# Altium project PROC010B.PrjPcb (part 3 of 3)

## Sheet PROC010C_XDS110 Interface_1B.SchDoc: XDS110 Interface_1B
size 431 x 279 mm; Date: Not shown in title block; ApprovedBy: Not shown in title block; CheckedBy: Not shown in title block; Author: Not shown in title block; CompanyName: Not shown in title block; DrawnBy: Adrian Ozer; Engineer: Not shown in title block; Organization: Not shown in title block; Address1: Not shown in title block; Address2: Not shown in title block; Address3: Not shown in title block; Address4: Not shown in title block; DocumentNumber: 13; Revision: Use project parameter SCH_Rev; SheetNumber: 13; SheetTotal: 16; PageSetup: Record=PageOptions¦CenterHorizontal=True¦CenterVertical=True¦PrintScale=1.00¦XCorrection=1.00¦YCorrection=1.00¦PrintKind=0¦BorderSize=5000000¦LeftOffset=0¦BottomOffset=0¦Orientation=2¦PaperLength=1000¦PaperWidth=1000¦Scale=100¦PaperSource=15¦PrintQuality=600¦MediaType=1¦DitherType=10¦PaperKind=Letter¦PrintScaleMode=1
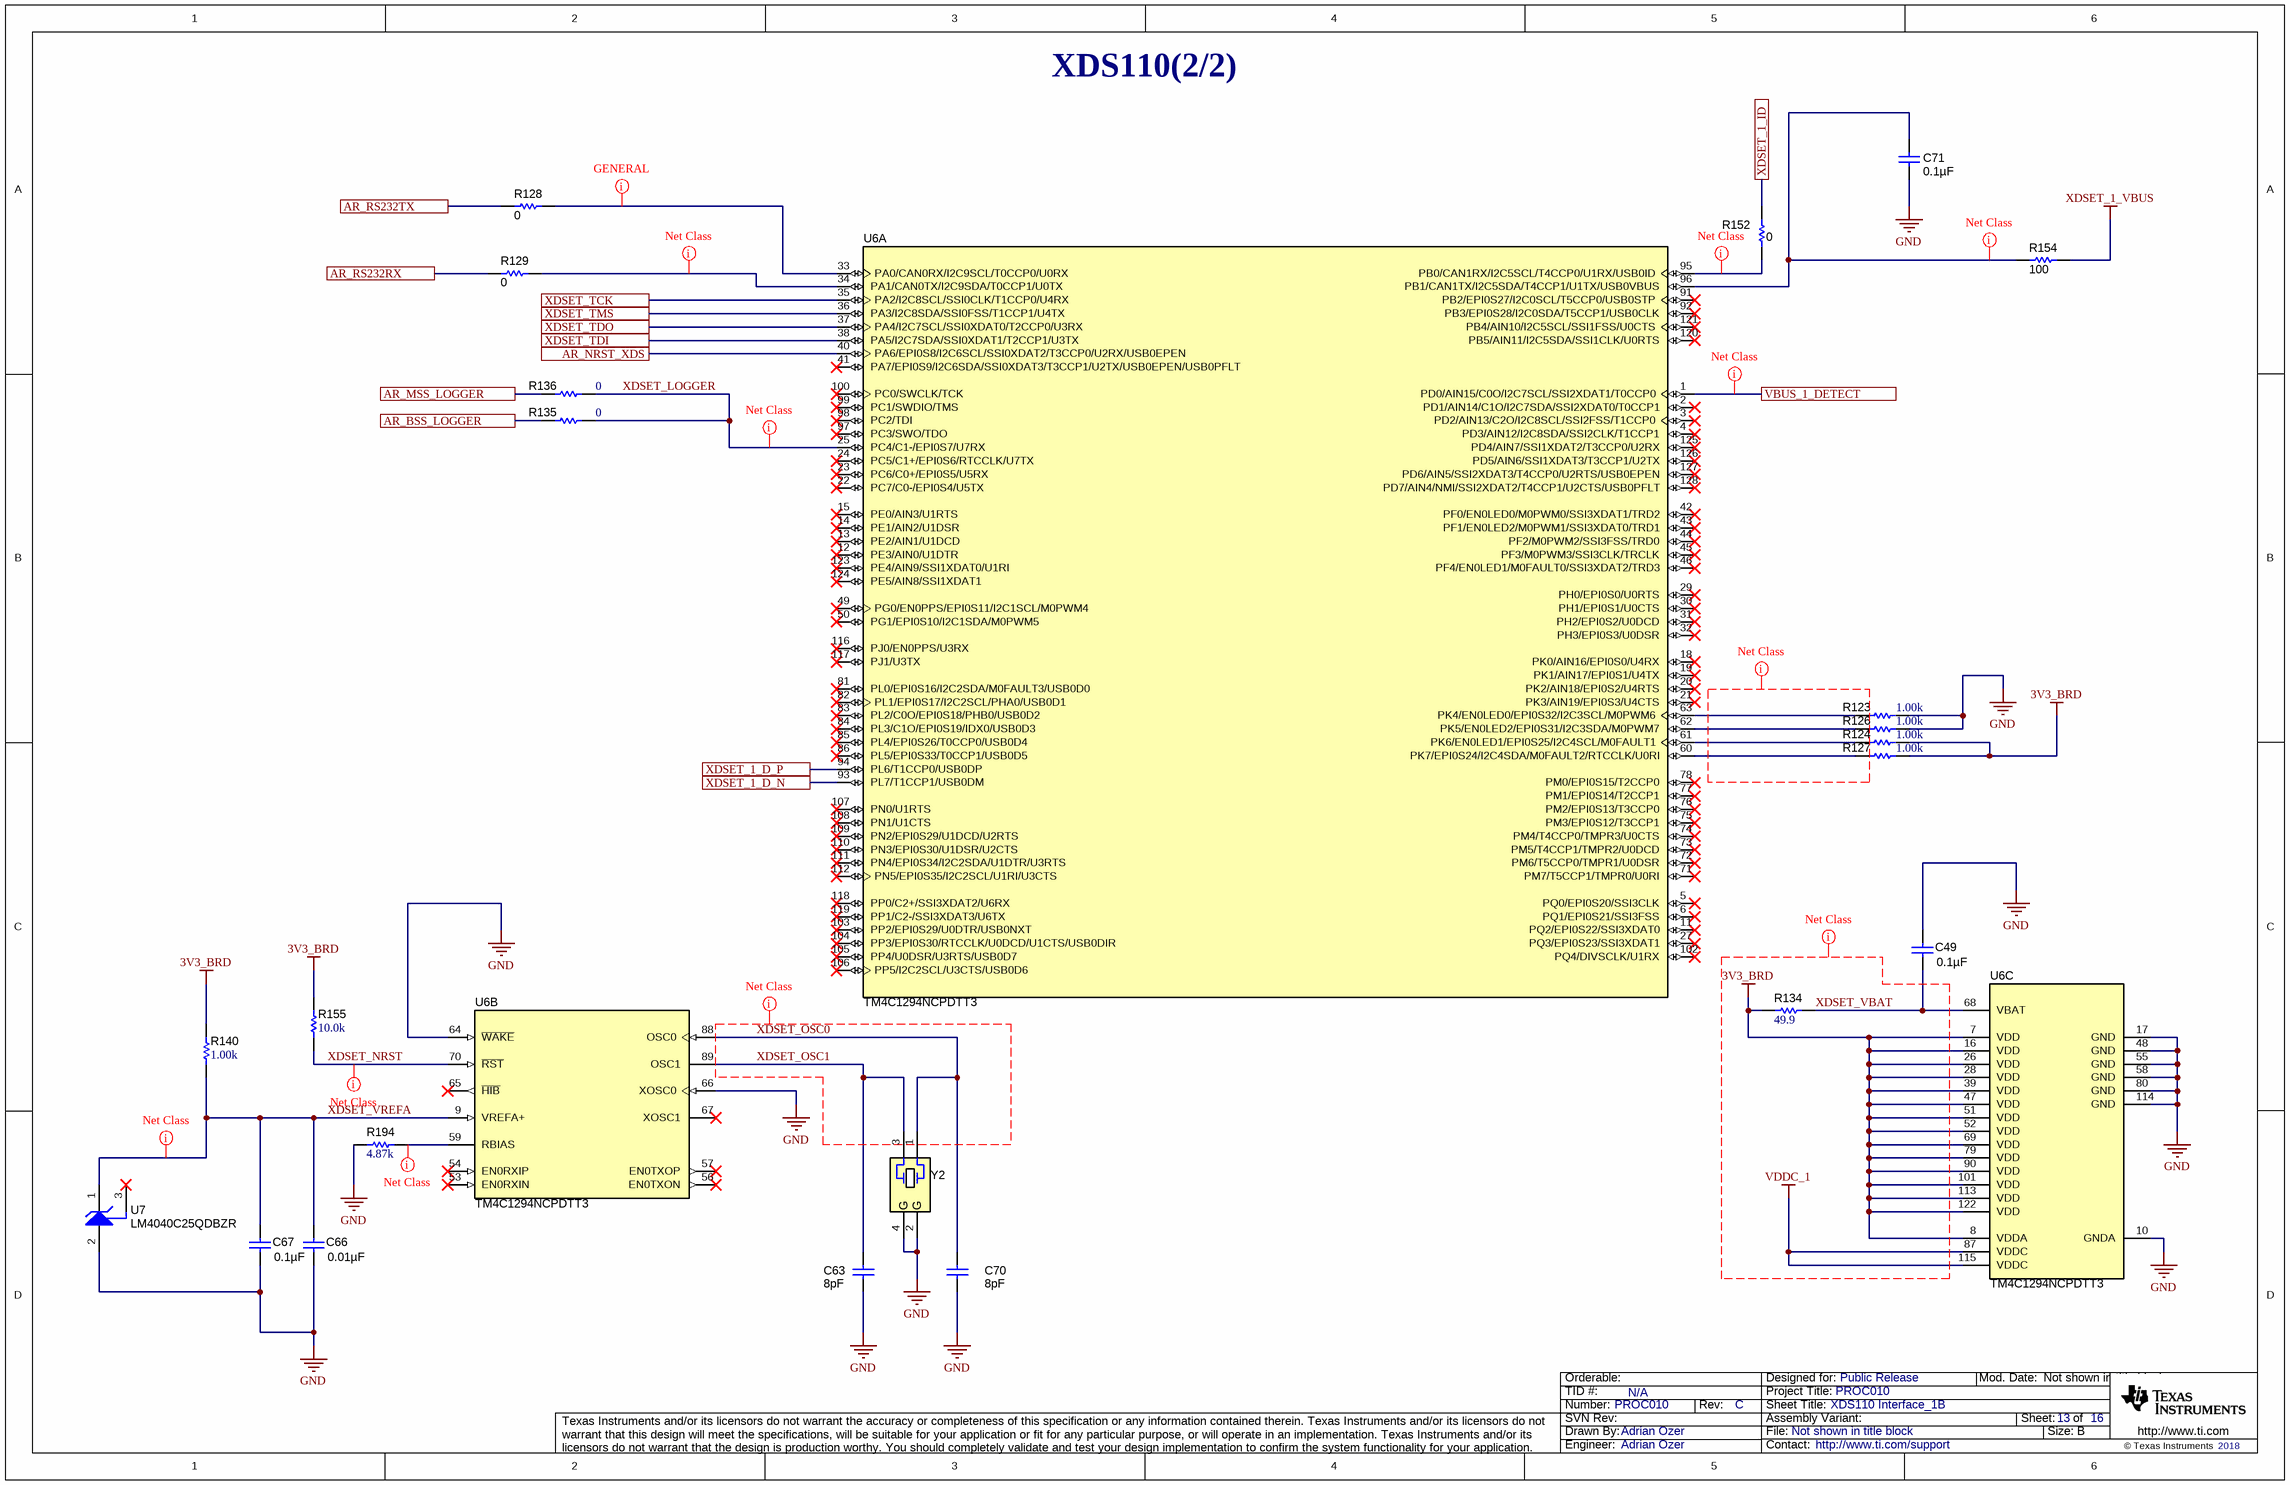
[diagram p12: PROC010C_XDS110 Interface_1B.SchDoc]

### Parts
C49  ValueDisplayed: 0.1µF  [0402L]  (hidden comment: C0402C104K8RACTU)
C63  ValueDisplayed: 8pF  [0402L]  (hidden comment: GRM1555C1H8R0DA01D)
C66  ValueDisplayed: 0.01µF  [0402L]  (hidden comment: C0402C103K4RACTU)
C67  ValueDisplayed: 0.1µF  [0402L]  (hidden comment: C0402C104K8RACTU)
C70  ValueDisplayed: 8pF  [0402L]  (hidden comment: GRM1555C1H8R0DA01D)
C71  ValueDisplayed: 0.1µF  [0402L]  (hidden comment: C0402C104K8RACTU)
R123  ValueDisplayed: 1.00k  [0402L]  (hidden comment: CRCW04021K00FKED)
R124  ValueDisplayed: 1.00k  [0402L]  (hidden comment: CRCW04021K00FKED)
R126  ValueDisplayed: 1.00k  [0402L]  (hidden comment: CRCW04021K00FKED)
R127  ValueDisplayed: 1.00k  [0402L]  (hidden comment: CRCW04021K00FKED)
R128  ValueDisplayed: 0  [0402L]  (hidden comment: ERJ-2GE0R00X)
R129  ValueDisplayed: 0  [0402L]  (hidden comment: ERJ-2GE0R00X)
R134  ValueDisplayed: 49.9  [0402L]  (hidden comment: CRCW040249R9FKED)
R135  ValueDisplayed: 0  [0201_Silk]  (hidden comment: CRCW02010000Z0ED)
R136  ValueDisplayed: 0  [0201_Silk]  (hidden comment: CRCW02010000Z0ED)
R140  ValueDisplayed: 1.00k  [0402L]  (hidden comment: CRCW04021K00FKED)
R152  ValueDisplayed: 0  [0402L]  (hidden comment: ERJ-2GE0R00X)
R154  ValueDisplayed: 100  [0402L]  (hidden comment: ERJ-2GEJ101X)
R155  ValueDisplayed: 10.0k  [0402L]  (hidden comment: CRCW040210K0FKED)
R194  ValueDisplayed: 4.87k  [0402L]  (hidden comment: CRCW04024K87FKED)
U6  TM4C1294NCPDTT3  [PDT0128A]  (parts A,B,C of 3)
U7  LM4040C25QDBZR  [DBZ0003A_N]
Y2  NX3225SA-16.000M-STD-CRS-2  [NDK_NX3225SA]  (value not drawn)

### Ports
AR_BSS_LOGGER, AR_MSS_LOGGER, AR_NRST_XDS, AR_RS232RX, AR_RS232TX, VBUS_1_DETECT, XDSET_1_D_N, XDSET_1_D_P, XDSET_1_ID, XDSET_TCK, XDSET_TDI, XDSET_TDO, XDSET_TMS

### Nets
3V3_BRD: R124.2 R127.2 R134.2 R140.2 R155.2 U6.7(VDD) U6.8(VDDA) U6.16(VDD) U6.26(VDD) U6.28(VDD) U6.39(VDD) U6.47(VDD) U6.51(VDD) U6.52(VDD) U6.69(VDD) U6.79(VDD) U6.90(VDD) U6.101(VDD) U6.113(VDD) U6.122(VDD)
GND: C49.1 C63.1 C66.1 C67.1 C70.1 C71.1 R123.2 R126.2 R194.1 U6.10(GNDA) U6.17(GND) U6.48(GND) U6.55(GND) U6.58(GND) U6.64(~{WAKE}) U6.66(XOSC0) U6.80(GND) U6.114(GND) U7.2(ANODE) Y2.2(GND) Y2.4(GND)
VDDC_1: U6.87(VDDC) U6.115(VDDC)
XDSET_1_VBUS: R154.2
AR_BSS_LOGGER: R135.1 ; port AR_BSS_LOGGER
AR_MSS_LOGGER: R136.1 ; port AR_MSS_LOGGER
AR_NRST_XDS: U6.40(PA6/EPI0S8/I2C6SCL/SSI0XDAT2/T3CCP0/U2RX/USB0EPEN) ; port AR_NRST_XDS
AR_RS232RX: R129.1 ; port AR_RS232RX
AR_RS232TX: R128.1 ; port AR_RS232TX
VBUS_1_DETECT: U6.1(PD0/AIN15/C0O/I2C7SCL/SSI2XDAT1/T0CCP0) ; port VBUS_1_DETECT
XDSET_1_D_N: U6.93(PL7/T1CCP1/USB0DM) ; port XDSET_1_D_N
XDSET_1_D_P: U6.94(PL6/T1CCP0/USB0DP) ; port XDSET_1_D_P
XDSET_1_ID: R152.2 ; port XDSET_1_ID
XDSET_LOGGER: R135.2 R136.2 U6.25(PC4/C1-/EPI0S7/U7RX)
XDSET_NRST: R155.1 U6.70(~{RST})
XDSET_OSC0: C70.2 U6.88(OSC0) Y2.1
XDSET_OSC1: C63.2 U6.89(OSC1) Y2.3
XDSET_TCK: U6.35(PA2/I2C8SCL/SSI0CLK/T1CCP0/U4RX) ; port XDSET_TCK
XDSET_TDI: U6.38(PA5/I2C7SDA/SSI0XDAT1/T2CCP1/U3TX) ; port XDSET_TDI
XDSET_TDO: U6.37(PA4/I2C7SCL/SSI0XDAT0/T2CCP0/U3RX) ; port XDSET_TDO
XDSET_TMS: U6.36(PA3/I2C8SDA/SSI0FSS/T1CCP1/U4TX) ; port XDSET_TMS
XDSET_VBAT: C49.2 R134.1 U6.68(VBAT)
XDSET_VREFA: C66.2 C67.2 R140.1 U6.9(VREFA+) U7.1(CATHODE)
NetC71_2: C71.2 R154.1 U6.96(PB1/CAN1TX/I2C5SDA/T4CCP1/U1TX/USB0VBUS)
NetR123_1: R123.1 U6.63(PK4/EN0LED0/EPI0S32/I2C3SCL/M0PWM6)
NetR124_1: R124.1 U6.61(PK6/EN0LED1/EPI0S25/I2C4SCL/M0FAULT1)
NetR126_1: R126.1 U6.62(PK5/EN0LED2/EPI0S31/I2C3SDA/M0PWM7)
NetR127_1: R127.1 U6.60(PK7/EPI0S24/I2C4SDA/M0FAULT2/RTCCLK/U0RI)
NetR128_2: R128.2 U6.33(PA0/CAN0RX/I2C9SCL/T0CCP0/U0RX)
NetR129_2: R129.2 U6.34(PA1/CAN0TX/I2C9SDA/T0CCP1/U0TX)
NetR152_1: R152.1 U6.95(PB0/CAN1RX/I2C5SCL/T4CCP0/U1RX/USB0ID)
NetR194_2: R194.2 U6.59(RBIAS)

Not connected (* = marked no-connect by the designer): U6 2(PD1/AIN14/C1O/I2C7SDA/SSI2XDAT0/T0CCP1)* 3(PD2/AIN13/C2O/I2C8SCL/SSI2FSS/T1CCP0)* 4(PD3/AIN12/I2C8SDA/SSI2CLK/T1CCP1)* 5(PQ0/EPI0S20/SSI3CLK)* 6(PQ1/EPI0S21/SSI3FSS)* 11(PQ2/EPI0S22/SSI3XDAT0)* 12(PE3/AIN0/U1DTR)* 13(PE2/AIN1/U1DCD)* 14(PE1/AIN2/U1DSR)* 15(PE0/AIN3/U1RTS)* 18(PK0/AIN16/EPI0S0/U4RX)* 19(PK1/AIN17/EPI0S1/U4TX)* 20(PK2/AIN18/EPI0S2/U4RTS)* 21(PK3/AIN19/EPI0S3/U4CTS)* 22(PC7/C0-/EPI0S4/U5TX)* 23(PC6/C0+/EPI0S5/U5RX)* 24(PC5/C1+/EPI0S6/RTCCLK/U7TX)* 27(PQ3/EPI0S23/SSI3XDAT1)* 29(PH0/EPI0S0/U0RTS)* 30(PH1/EPI0S1/U0CTS)* 31(PH2/EPI0S2/U0DCD)* 32(PH3/EPI0S3/U0DSR)* 41(PA7/EPI0S9/I2C6SDA/SSI0XDAT3/T3CCP1/U2TX/USB0EPEN/USB0PFLT)* 42(PF0/EN0LED0/M0PWM0/SSI3XDAT1/TRD2)* 43(PF1/EN0LED2/M0PWM1/SSI3XDAT0/TRD1)* 44(PF2/M0PWM2/SSI3FSS/TRD0)* 45(PF3/M0PWM3/SSI3CLK/TRCLK)* 46(PF4/EN0LED1/M0FAULT0/SSI3XDAT2/TRD3)* 49(PG0/EN0PPS/EPI0S11/I2C1SCL/M0PWM4)* 50(PG1/EPI0S10/I2C1SDA/M0PWM5)* 53(EN0RXIN)* 54(EN0RXIP)* 56(EN0TXON)* 57(EN0TXOP)* 65(~{HIB})* 67(XOSC1)* 71(PM7/T5CCP1/TMPR0/U0RI)* 72(PM6/T5CCP0/TMPR1/U0DSR)* 73(PM5/T4CCP1/TMPR2/U0DCD)* 74(PM4/T4CCP0/TMPR3/U0CTS)* 75(PM3/EPI0S12/T3CCP1)* 76(PM2/EPI0S13/T3CCP0)* 77(PM1/EPI0S14/T2CCP1)* 78(PM0/EPI0S15/T2CCP0)* 81(PL0/EPI0S16/I2C2SDA/M0FAULT3/USB0D0)* 82(PL1/EPI0S17/I2C2SCL/PHA0/USB0D1)* 83(PL2/C0O/EPI0S18/PHB0/USB0D2)* 84(PL3/C1O/EPI0S19/IDX0/USB0D3)* 85(PL4/EPI0S26/T0CCP0/USB0D4)* 86(PL5/EPI0S33/T0CCP1/USB0D5)* 91(PB2/EPI0S27/I2C0SCL/T5CCP0/USB0STP)* 92(PB3/EPI0S28/I2C0SDA/T5CCP1/USB0CLK)* 97(PC3/SWO/TDO)* 98(PC2/TDI)* 99(PC1/SWDIO/TMS)* 100(PC0/SWCLK/TCK)* 102(PQ4/DIVSCLK/U1RX)* 103(PP2/EPI0S29/U0DTR/USB0NXT)* 104(PP3/EPI0S30/RTCCLK/U0DCD/U1CTS/USB0DIR)* 105(PP4/U0DSR/U3RTS/USB0D7)* 106(PP5/I2C2SCL/U3CTS/USB0D6)* 107(PN0/U1RTS)* 108(PN1/U1CTS)* 109(PN2/EPI0S29/U1DCD/U2RTS)* 110(PN3/EPI0S30/U1DSR/U2CTS)* 111(PN4/EPI0S34/I2C2SDA/U1DTR/U3RTS)* 112(PN5/EPI0S35/I2C2SCL/U1RI/U3CTS)* 116(PJ0/EN0PPS/U3RX)* 117(PJ1/U3TX)* 118(PP0/C2+/SSI3XDAT2/U6RX)* 119(PP1/C2-/SSI3XDAT3/U6TX)* 120(PB5/AIN11/I2C5SDA/SSI1CLK/U0RTS)* 121(PB4/AIN10/I2C5SCL/SSI1FSS/U0CTS)* 123(PE4/AIN9/SSI1XDAT0/U1RI)* 124(PE5/AIN8/SSI1XDAT1)* 125(PD4/AIN7/SSI1XDAT2/T3CCP0/U2RX)* 126(PD5/AIN6/SSI1XDAT3/T3CCP1/U2TX)* 127(PD6/AIN5/SSI2XDAT3/T4CCP0/U2RTS/USB0EPEN)* 128(PD7/AIN4/NMI/SSI2XDAT2/T4CCP1/U2CTS/USB0PFLT)*; U7 3(NC)*

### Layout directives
net class GENERAL: (no net found under the mark), NetC71_2, NetR129_2, NetR152_1, NetR194_2, VBUS_1_DETECT, XDSET_LOGGER, XDSET_NRST
net class PWR: 3V3_BRD, VDDC_1, XDSET_VBAT, XDSET_VREFA
net class CLK: GND, XDSET_OSC0, XDSET_OSC1
net class Undefined: NetR128_2

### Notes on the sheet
- XDS110(2/2)

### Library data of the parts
C49 = CMP-0078241-1: CAP, CERM, 0.1 µF, 10 V,+/- 10%, X7R, 0402; Manufacturer: Kemet; TaMin_C: -55°C; Polarized: N; SizeAreaWB_mm2: 3; U/M: EA; Value: 0.1uF; TaMax_C: 125°C; SizeZ_mm: 0.6; SizeX_mm: 1; SizeY_mm: 0.5; Cap_Case: 0402; Value2: 10V; CompType: Capacitor; Cap_F: 100nF; AEC Category: Q200
C63 C70 = CMP-0006494-2: CAP, CERM, 8 pF, 50 V, +/- 6%, C0G/NP0, 0402; Manufacturer: MuRata; TaMin_C: -55°C; Polarized: N; SizeAreaWB_mm2: 3; Value1: Unknown; U/M: EA; Value: 8pF; TaMax_C: 125°C; SizeZ_mm: 0.6; SizeX_mm: 1; SizeY_mm: 0.5; Cap_Case: 0402; Value2: 50V; CompType: Capacitor; AEC Category: Q200
C66 = CMP-0078218-1: CAP, CERM, 0.01 µF, 16 V,+/- 10%, X7R, 0402; Manufacturer: Kemet; TaMin_C: -55°C; Polarized: N; Green_Lifecycle: Active; SizeAreaWB_mm2: 3; Green_REACh: Passed; U/M: EA; Value: 0.01uF; TaMax_C: 125°C; SizeZ_mm: 0.6; SizeX_mm: 1; SizeY_mm: 0.5; Cap_Case: 0402; Value2: 16V; Cap_F: 10nF; AEC Category: Q200
C67 C71 = CMP-0078241-1: CAP, CERM, 0.1 µF, 10 V,+/- 10%, X7R, 0402; Manufacturer: Kemet; TaMin_C: -55°C; Polarized: N; SizeAreaWB_mm2: 3; U/M: EA; Value: 0.1uF; TaMax_C: 125°C; SizeZ_mm: 0.6; SizeX_mm: 1; SizeY_mm: 0.5; Cap_Case: 0402; Value2: 10V; Cap_F: 100nF; AEC Category: Q200
R123 R124 R126 R127 R140 = CMP-0026071-3: RES, 1.00 k, 1%, 0.063 W, AEC-Q200 Grade 0, 0402; Manufacturer: Vishay-Dale; Power_W: 63mW; TempCo: 100 ppm/C; Value_Code: 1k00; Value: 1.00k; EIA_Code: E96; Res_ohm: 1k; SizeX_mm: 1; SizeY_mm: 0.5; SizeZ_mm: 0.6; Value2: 0.063W; AEC Qualified: Y; VDC_V: 50V; AEC Category: Q200; AEC Grade: 0
R128 R129 R152 = CMP-0026992-2: RES, 0, 5%, 0.063 W, 0402; Manufacturer: Panasonic; Power_W: 63mW; TempCo: 600 ppm/C; Value_Code: 0000; U/M: EA; Value: 0; EIA_Code: E24; SizeX_mm: 1; SizeY_mm: 0.5; SizeZ_mm: 0.6; Value2: 0.063W; VDC_V: 50V; AEC Category: Q200
R134 = CMP-0026404-2: RES, 49.9, 1%, 0.063 W, AEC-Q200 Grade 0, 0402; Manufacturer: Vishay-Dale; Power_W: 63mW; TempCo: 100 ppm/C; Value_Code: 49R9; Value: 49.9; EIA_Code: E96; SizeX_mm: 1; SizeY_mm: 0.5; SizeZ_mm: 0.6; Value2: 0.063W; AEC Qualified: Y; VDC_V: 50V; AEC Category: Q200; AEC Grade: 0
R135 R136 = CMP-0027008-4: RES, 0, 5%, 0.05 W, 0201; Manufacturer: Vishay-Dale; Power_W: 50mW; TempCo: ppm/C; Value_Code: 0000; Value: 0; EIA_Code: E24; SizeX_mm: 0.6; SizeY_mm: 0.3; SizeZ_mm: 0.26; Value2: 0.05W; SizeArea_mm2: 0.18; AEC Qualified: N; AEC Category: Q200
R154 = CMP-0026993-2: RES, 100, 5%, 0.1 W, AEC-Q200 Grade 0, 0402; Manufacturer: Panasonic; Power_W: 100mW; TempCo: 200 ppm/C; Value_Code: 100R; U/M: EA; Value: 100; EIA_Code: E24; SizeX_mm: 1; SizeY_mm: 0.5; SizeZ_mm: 0.6; Value2: 0.1W; AEC Qualified: Y; AEC Grade: 0; AEC Category: Q200
R155 = CMP-0025958-3: RES, 10.0 k, 1%, 0.063 W, AEC-Q200 Grade 0, 0402; Manufacturer: Vishay-Dale; Power_W: 63mW; TempCo: 100 ppm/C; Value_Code: 10k0; Value: 10.0k; EIA_Code: E96; Res_ohm: 10k; SizeX_mm: 1; SizeY_mm: 0.5; SizeZ_mm: 0.6; Value2: 0.063W; AEC Qualified: Y; VDC_V: 50V; AEC Category: Q200; AEC Grade: 0
R194 = CMP-0026413-2: RES, 4.87 k, 1%, 0.063 W, AEC-Q200 Grade 0, 0402; Manufacturer: Vishay-Dale; Power_W: 63mW; TempCo: 100 ppm/C; Value_Code: 4k87; Value: 4.87k; EIA_Code: E96; SizeX_mm: 1; SizeY_mm: 0.5; SizeZ_mm: 0.6; Value2: 0.063W; AEC Qualified: Y; VDC_V: 50V; AEC Category: Q200; AEC Grade: 0
U6 = CMP-0029856-2: Tiva C Series Microcontroller, 1024 KB Flash, 256 KB SRAM, 12 Bit, 20 Channels, -40 to 105 degC, 128-Pin TQFP (PDT), Green (RoHS & no Sb/Br), Tray; Manufacturer: Texas Instruments; ADC Channels: 20; CPU: ARM Cortex-M4; Flash: 1024 KB; ADC Resolution: 12 Bits; Max Speed: 120 MHz; SRAM: 256 KB; SizeAreaWB_mm2: 324.0; SizeArea_mm2: 256.0; SizeX_mm: 16.0; SizeZ_mm: 1.2; CompType: IC
U7 = CMP-0033001-1: Precision Micropower Shunt Voltage Reference, 0.5% accuracy, 2.5 V, 15 ppm / degC, 15 mA, -40 to 125 degC, 3-pin SOT-23 (DBZ), Green (RoHS & no Sb/Br); Manufacturer: Texas Instruments; Initial Accuracy @ 25/deg C(%): 0.5; Temp Coeff(Typ)(ppm/ degree C): 15; Temp Coeff(Max)(ppm/ degree C): 100; Rating: Catalog; Min Iz for Regulation(uA): 75; VO(V): 2.5
Y2 = CMP-0078214-2: Crystal, 16 MHz, 15 ppm, 8 pF, AEC-Q200 Grade 1, SMD; Manufacturer: NDK; TaMin_C: -40°C; Frequency Tolerance: 10 ppm; Frequency Stability: 150 ppm; Load Capacitance: 7.36 pF; Frequency_Fixed: 16MHz; TaMax_C: 125°C; AEC Qualified: N; AEC Grade: 1; AEC Category: Q200

## Sheet PROC010C_CAN Interface.SchDoc: CAN Interface
size 431 x 279 mm; Date: Not shown in title block; ApprovedBy: Not shown in title block; CheckedBy: Not shown in title block; Author: Not shown in title block; CompanyName: Not shown in title block; DrawnBy: Adrian Ozer; Engineer: Not shown in title block; Organization: Not shown in title block; Address1: Not shown in title block; Address2: Not shown in title block; Address3: Not shown in title block; Address4: Not shown in title block; DocumentNumber: 14; Revision: Use project parameter SCH_Rev; SheetNumber: 14; SheetTotal: 16; PageSetup: Record=PageOptions¦CenterHorizontal=True¦CenterVertical=True¦PrintScale=1.00¦XCorrection=1.00¦YCorrection=1.00¦PrintKind=0¦BorderSize=5000000¦LeftOffset=0¦BottomOffset=0¦Orientation=2¦PaperLength=1000¦PaperWidth=1000¦Scale=100¦PaperSource=15¦PrintQuality=600¦MediaType=1¦DitherType=10¦PaperKind=Letter¦PrintScaleMode=1
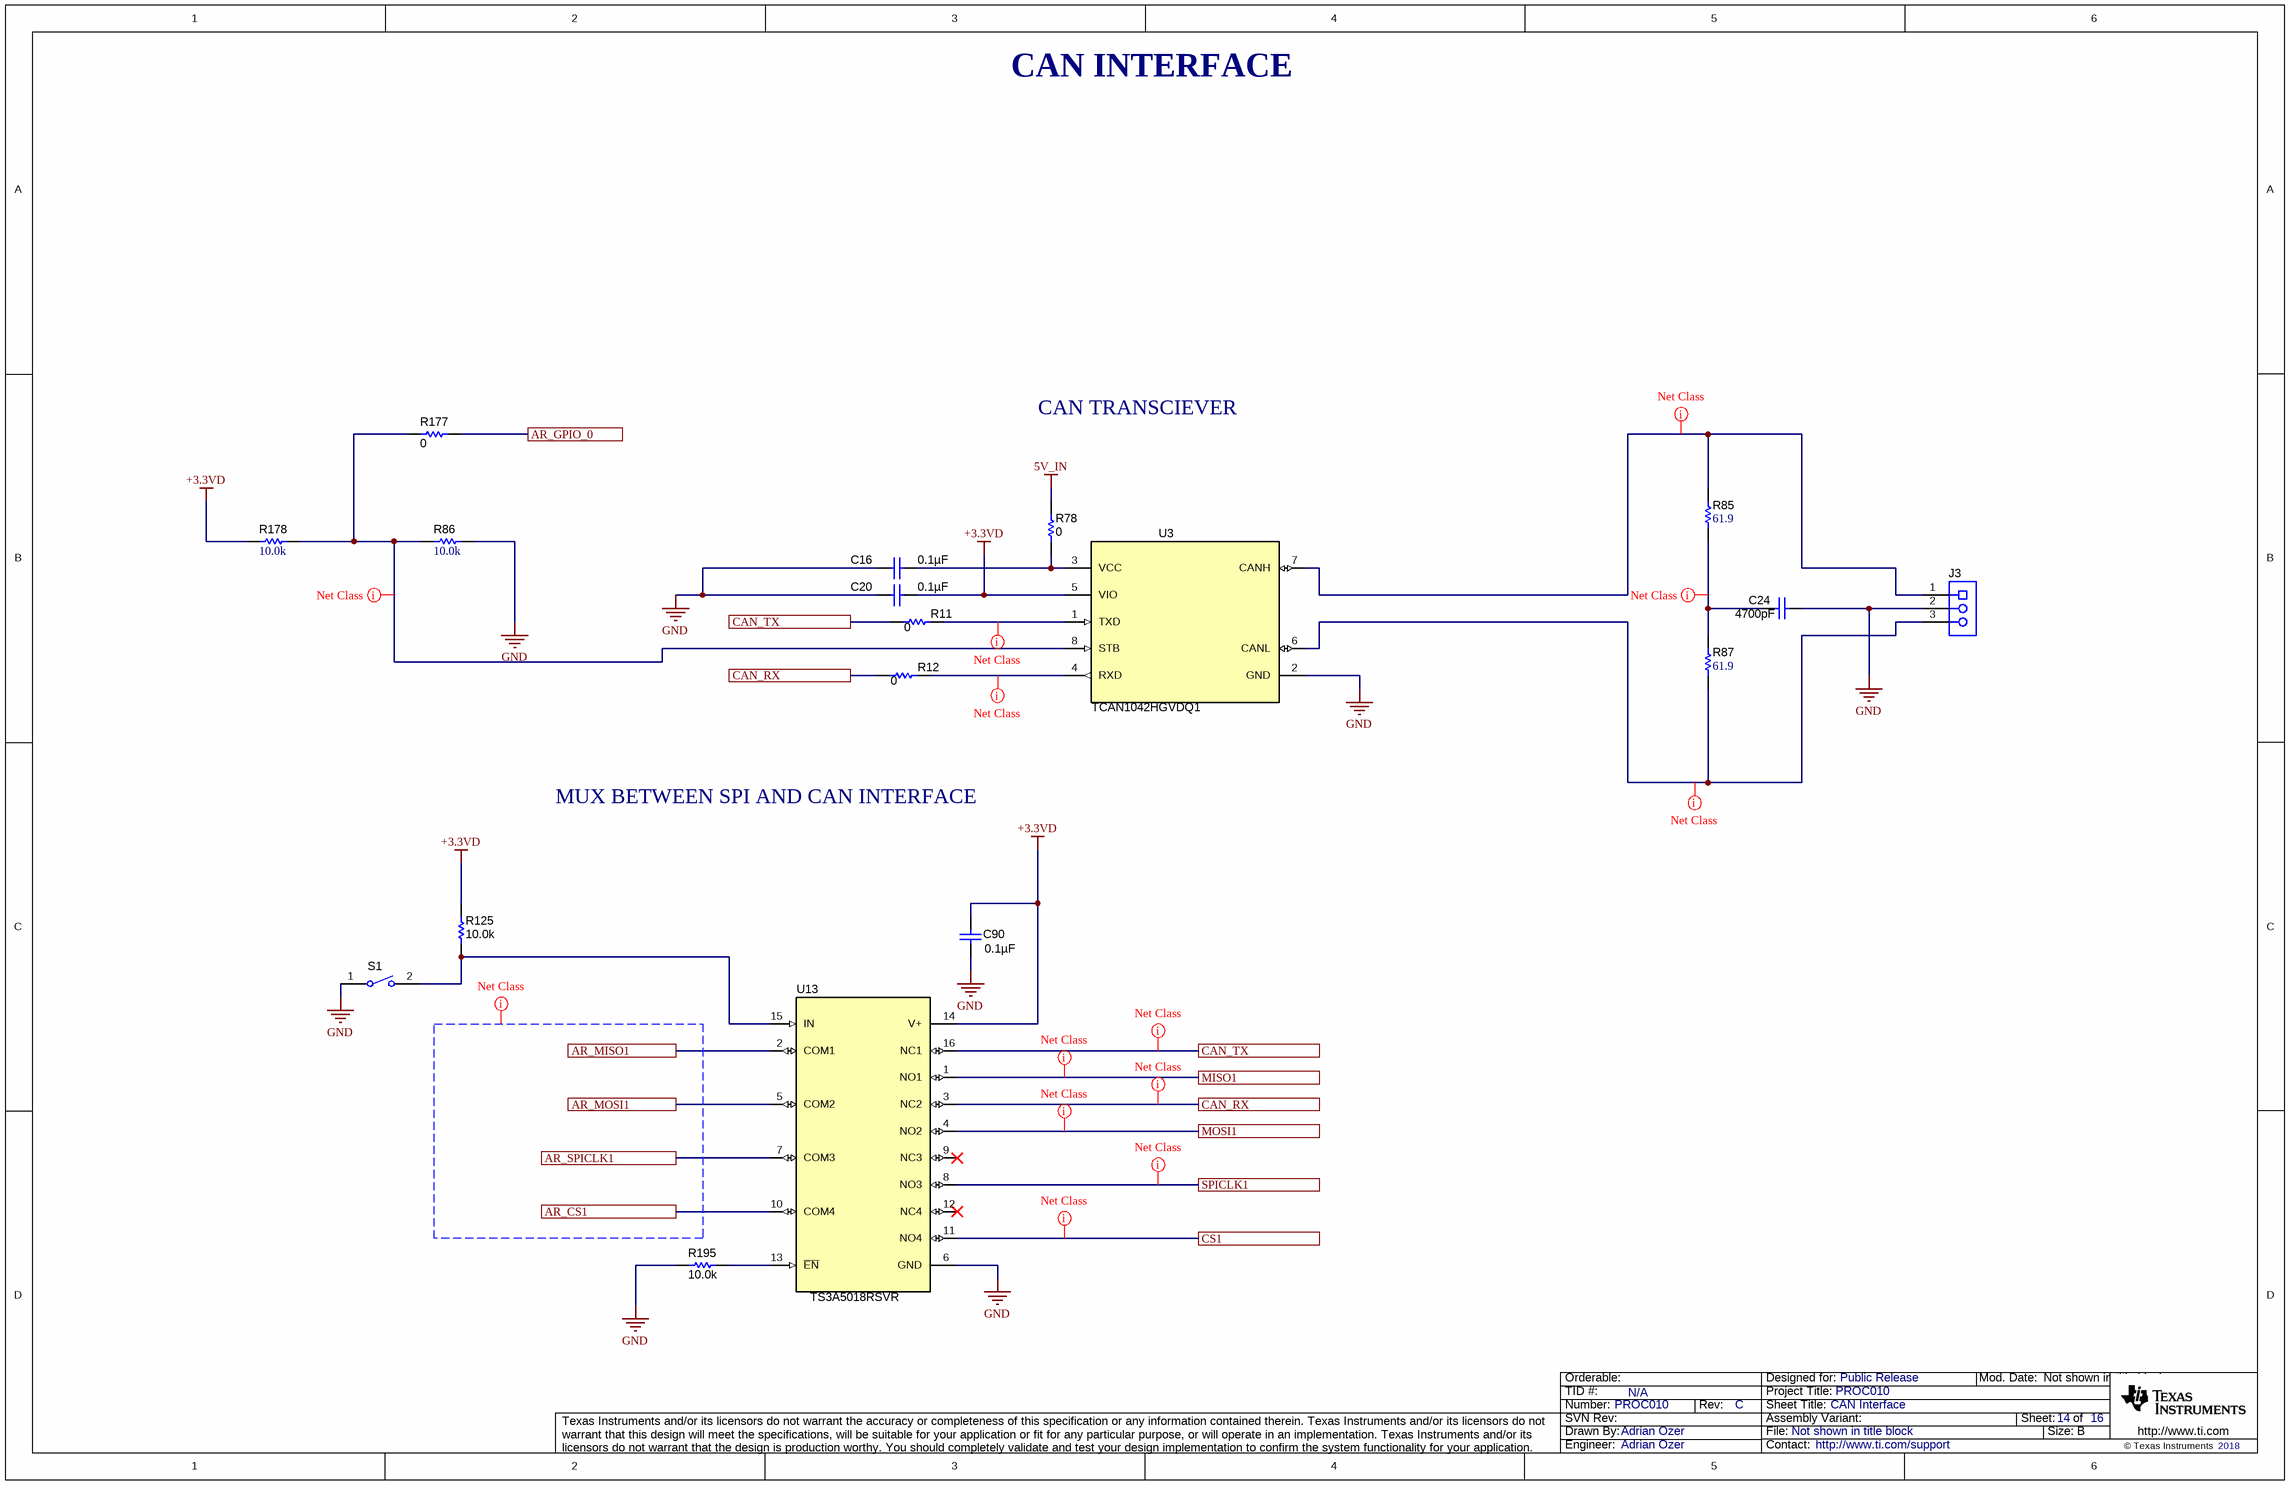
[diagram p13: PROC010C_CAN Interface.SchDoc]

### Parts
C16  ValueDisplayed: 0.1µF  [0402L]  (hidden comment: C0402C104K8RACTU)
C20  ValueDisplayed: 0.1µF  [0402L]  (hidden comment: C0402C104K8RACTU)
C24  ValueDisplayed: 4700pF  [0402L]  (hidden comment: C1005X7R1H472K050BA)
C90  ValueDisplayed: 0.1µF  [0402L]  (hidden comment: C0402C104K8RACTU)
J3  OSTTE030161  [On-Shore_OSTTE030161]  (value not drawn)
R11  ValueDisplayed: 0  [0402L]  (hidden comment: ERJ-2GE0R00X)
R12  ValueDisplayed: 0  [0402L]  (hidden comment: ERJ-2GE0R00X)
R78  ValueDisplayed: 0  [0402L]  (hidden comment: ERJ-2GE0R00X)
R85  ValueDisplayed: 61.9  [0402L]  (hidden comment: CRCW040261R9FKED)
R86  ValueDisplayed: 10.0k  [0402L]  (hidden comment: CRCW040210K0FKED)
R87  ValueDisplayed: 61.9  [0402L]  (hidden comment: CRCW040261R9FKED)
R125  ValueDisplayed: 10.0k  [0402L]  (hidden comment: CRCW040210K0FKED)
R177  ValueDisplayed: 0  [0402L]  (hidden comment: ERJ-2GE0R00X)
R178  ValueDisplayed: 10.0k  [0402L]  (hidden comment: CRCW040210K0FKED)
R195  ValueDisplayed: 10.0k  [0402L]  (hidden comment: CRCW040210K0FKED)
S1  CHS-01TB  [SW_CHS-01TB]  (value not drawn)
U3  TCAN1042HGVDQ1  [D0008A_L]
U13  TS3A5018RSVR  [RSV0016A]

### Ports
AR_CS1, AR_GPIO_0, AR_MISO1, AR_MOSI1, AR_SPICLK1, CAN_RX, CAN_TX, CS1, MISO1, MOSI1, SPICLK1

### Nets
5V_IN: R78.2
+3.3VD: C20.2 C90.2 R125.2 R178.1 U3.5(VIO) U13.14(V+)
GND: C16.1 C20.1 C24.1 C90.1 J3.2 R86.2 R195.2 S1.1 U3.2(GND) U13.6(GND)
AR_CS1: U13.10(COM4) ; port AR_CS1
AR_GPIO_0: R177.2 ; port AR_GPIO_0
AR_MISO1: U13.2(COM1) ; port AR_MISO1
AR_MOSI1: U13.5(COM2) ; port AR_MOSI1
AR_SPICLK1: U13.7(COM3) ; port AR_SPICLK1
CAN_RX: R12.1 U13.3(NC2) ; port CAN_RX
CAN_TX: R11.1 U13.16(NC1) ; port CAN_TX
CS1: U13.11(NO4) ; port CS1
MISO1: U13.1(NO1) ; port MISO1
MOSI1: U13.4(NO2) ; port MOSI1
SPICLK1: U13.8(NO3) ; port SPICLK1
NetC16_2: C16.2 R78.1 U3.3(VCC)
NetC24_2: C24.2 R85.1 R87.2
NetJ3_1: J3.1 R85.2 U3.7(CANH)
NetJ3_3: J3.3 R87.1 U3.6(CANL)
NetR11_2: R11.2 U3.1(TXD)
NetR12_2: R12.2 U3.4(RXD)
NetR86_1: R86.1 R177.1 R178.2 U3.8(STB)
NetR125_1: R125.1 S1.2 U13.15(IN)
NetR195_1: R195.1 U13.13(~{EN})

Not connected (* = marked no-connect by the designer): U13 9(NC3)* 12(NC4)*

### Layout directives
net class CAN: CAN_RX, CAN_TX, NetC24_2, NetJ3_1, NetJ3_3, NetR11_2, NetR12_2
net class GENERAL: NetR86_1
net class SPI: (no net found under the mark), CS1, MISO1, MOSI1, SPICLK1

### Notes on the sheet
- CAN INTERFACE
- CAN TRANSCIEVER
- MUX BETWEEN SPI AND CAN INTERFACE

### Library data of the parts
C16 C20 C90 = CMP-0078241-1: as C67 on sheet PROC010C_XDS110 Interface_1B
C24 = CMP-0078221-1: CAP, CERM, 4700 pF, 50 V,+/- 10%, X7R, 0402; Manufacturer: TDK; TaMin_C: -55°C; Polarized: N; SizeAreaWB_mm2: 3; U/M: EA; Value: 4700pF; TaMax_C: 125°C; SizeZ_mm: 0.6; SizeX_mm: 1; SizeY_mm: 0.5; Cap_Case: 0402; Value2: 50V; Cap_F: 4.7nF; AEC Category: Q200
J3 = CMP-0075352-1: Terminal Block, 3.5mm, 3x1, Tin, R/A, TH; Manufacturer: On-Shore Technology; CNHeader: False; Current_A: 10A; Green_Lifecycle: Not Set; Gender: Female; Cert_CSA: Y; Green_REACh: Incomplete; Voltage_V: 125V; Row_Count: 1; Pitch_mm: 3.5; CT: True
R11 R12 R177 = CMP-0026992-2: RES, 0, 5%, 0.063 W, 0402; Manufacturer: Panasonic; Power_W: 63mW; TempCo: 600 ppm/C; Value_Code: 0000; U/M: EA; Value: 0; EIA_Code: E24; SizeX_mm: 1; SizeY_mm: 0.5; SizeZ_mm: 0.6; Value2: 0.063W; CompType: Resistor; VDC_V: 50V; AEC Category: Q200; INSTALATION: DNP
R78 = CMP-0026992-2: RES, 0, 5%, 0.063 W, 0402; Manufacturer: Panasonic; Power_W: 63mW; TempCo: 600 ppm/C; Value_Code: 0000; U/M: EA; Value: 0; EIA_Code: E24; SizeX_mm: 1; SizeY_mm: 0.5; SizeZ_mm: 0.6; Value2: 0.063W; CompType: Resistor; VDC_V: 50V; AEC Category: Q200
R85 R87 = CMP-0026491-2: RES, 61.9, 1%, 0.063 W, AEC-Q200 Grade 0, 0402; Manufacturer: Vishay-Dale; Power_W: 63mW; TempCo: 100 ppm/C; Value_Code: 61R9; Value: 61.9; EIA_Code: E96; SizeX_mm: 1; SizeY_mm: 0.5; SizeZ_mm: 0.6; Value2: 0.063W; AEC Qualified: Y; VDC_V: 50V; AEC Category: Q200; AEC Grade: 0
R86 R178 = CMP-0025958-3: as R155 on sheet PROC010C_XDS110 Interface_1B
R125 R195 = CMP-0025958-2: RES, 10.0 k, 1%, 0.063 W, 0402; Manufacturer: Vishay-Dale; Power_W: 63mW; TempCo: 100 ppm/C; Value_Code: 10k0; U/M: EA; Value: 10.0k; EIA_Code: E96; Res_ohm: 10k; SizeX_mm: 1; SizeY_mm: 0.5; SizeZ_mm: 0.6; Value2: 0.063W; CompType: Resistor; VDC_V: 50V; AEC Category: Q200
S1 = CMP-0002163-2: Switch, Slide, SPST, Top Slide, SMT; Manufacturer: Copal Electronics; CurrentRating_mA: 100A; SwitchFunction: Off-On; VDC_V: 6V; PositionCount: 1
U3 = CMP-0075992-1: Automotive Fault Protected CAN Transceiver With Flexible Data-Rate, D0008A (SOIC-8); Manufacturer: Texas Instruments; Alternate PartNumber: TCAN1042HGVDRQ1; SizeAreaWB_mm2: 56.58; SizeArea_mm2: 30.38; SizeZ_mm: 1.75; SizeY_mm: 6.2; U/M: EA; CompType: IC; SizeX_mm: 4.9
U13 = CMP-0067415-1: 10-Ohm Quad SPDT Analog Switch, RSV0016A (UQFN-16); Alternate Manufacturer: Texas Instruments; SizeAreaWB_mm2: 10.08; U/M: EA; SizeZ_mm: 0.55; SizeX_mm: 1.8; SizeY_mm: 2.6; SizeArea_mm2: 4.68; CompType: IC

## Sheet PROC010C_Tempsensor.SchDoc: Tempsensor
size 431 x 279 mm; Date: Not shown in title block; ApprovedBy: Not shown in title block; CheckedBy: Not shown in title block; Author: Not shown in title block; CompanyName: Not shown in title block; DrawnBy: Adrian Ozer; Engineer: Not shown in title block; Organization: Not shown in title block; Address1: Not shown in title block; Address2: Not shown in title block; Address3: Not shown in title block; Address4: Not shown in title block; DocumentNumber: 15; Revision: Use project parameter SCH_Rev; SheetNumber: 15; SheetTotal: 16; PageSetup: Record=PageOptions¦CenterHorizontal=True¦CenterVertical=True¦PrintScale=1.00¦XCorrection=1.00¦YCorrection=1.00¦PrintKind=0¦BorderSize=5000000¦LeftOffset=0¦BottomOffset=0¦Orientation=2¦PaperLength=1000¦PaperWidth=1000¦Scale=100¦PaperSource=15¦PrintQuality=600¦MediaType=1¦DitherType=10¦PaperKind=Letter¦PrintScaleMode=1
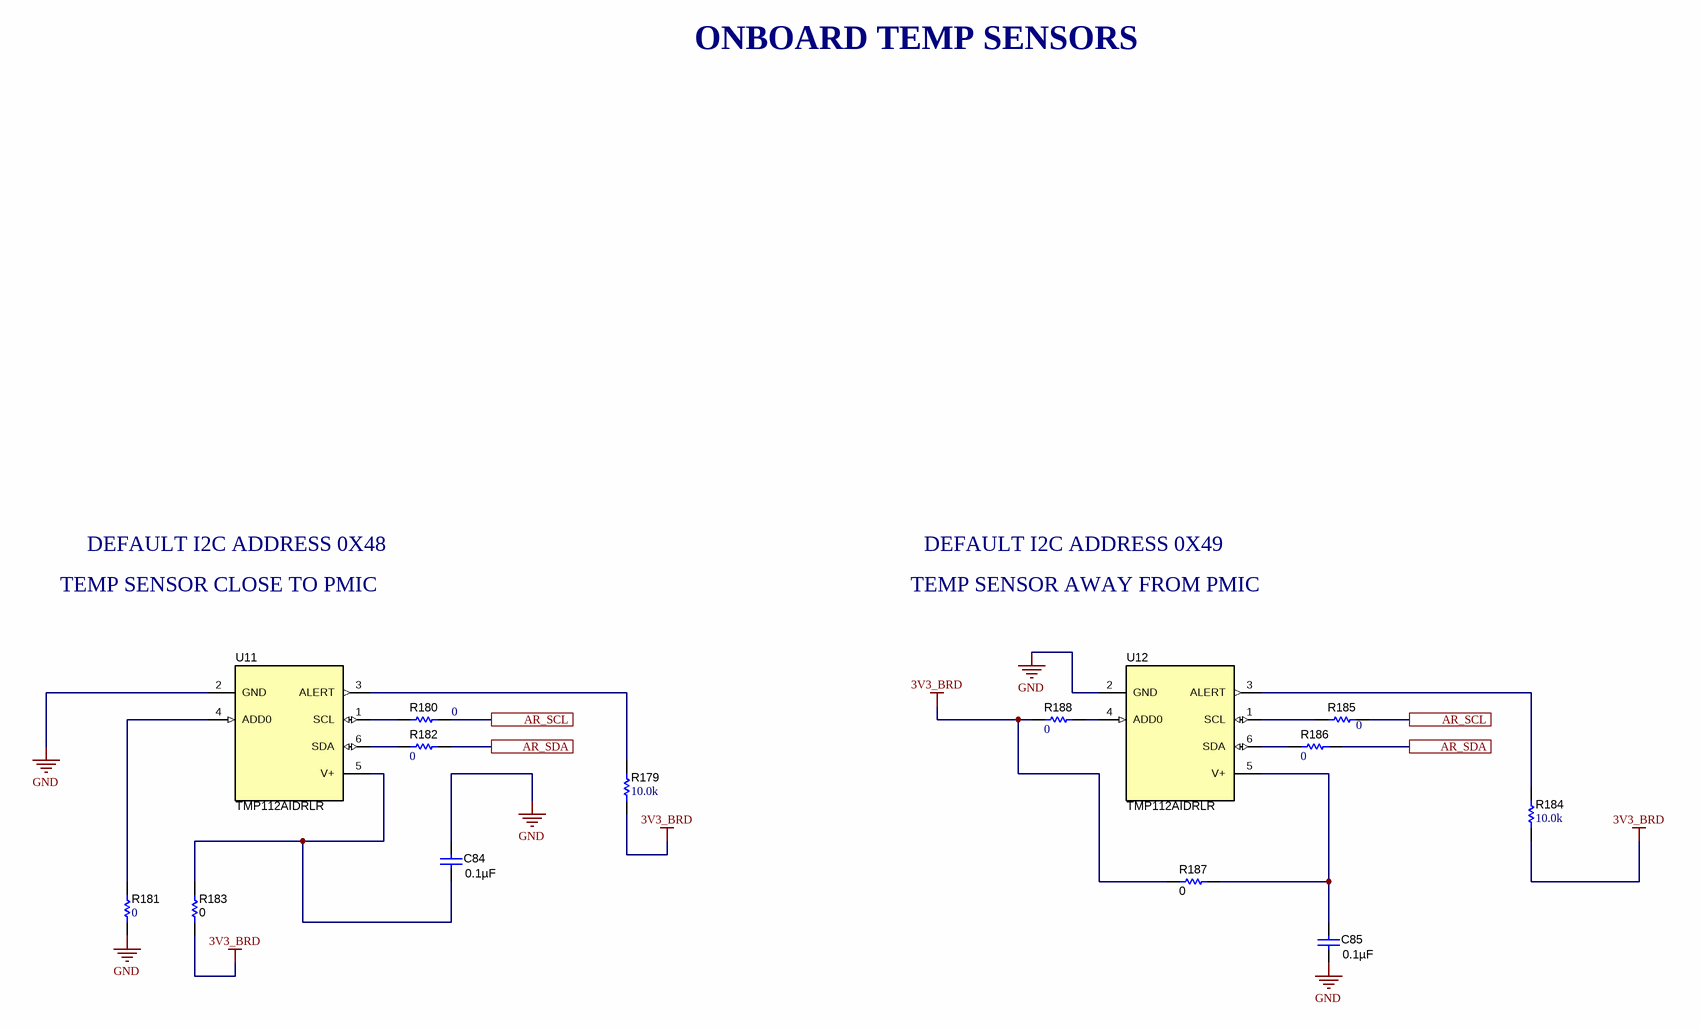
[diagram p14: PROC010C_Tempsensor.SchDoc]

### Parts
C84  ValueDisplayed: 0.1µF  [0402L]  (hidden comment: C0402C104K8RACTU)
C85  ValueDisplayed: 0.1µF  [0402L]  (hidden comment: C0402C104K8RACTU)
R179  ValueDisplayed: 10.0k  [0402L]  (hidden comment: CRCW040210K0FKED)
R180  ValueDisplayed: 0  [0201_Silk]  (hidden comment: CRCW02010000Z0ED)
R181  ValueDisplayed: 0  [0201_Silk]  (hidden comment: CRCW02010000Z0ED)
R182  ValueDisplayed: 0  [0201_Silk]  (hidden comment: CRCW02010000Z0ED)
R183  ValueDisplayed: 0  [0402L]  (hidden comment: ERJ-2GE0R00X)
R184  ValueDisplayed: 10.0k  [0402L]  (hidden comment: CRCW040210K0FKED)
R185  ValueDisplayed: 0  [0201_Silk]  (hidden comment: CRCW02010000Z0ED)
R186  ValueDisplayed: 0  [0201_Silk]  (hidden comment: CRCW02010000Z0ED)
R187  ValueDisplayed: 0  [0402L]  (hidden comment: ERJ-2GE0R00X)
R188  ValueDisplayed: 0  [0201_Silk]  (hidden comment: CRCW02010000Z0ED)
U11  TMP112AIDRLR  [DRL0006A]
U12  TMP112AIDRLR  [DRL0006A]

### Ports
AR_SCL, AR_SDA

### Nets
3V3_BRD: R179.2 R183.2 R184.2 R187.2 R188.1
GND: C84.1 C85.2 R181.2 U11.2(GND) U12.2(GND)
AR_SCL: R180.1 R185.1 ; port AR_SCL
AR_SDA: R182.2 R186.2 ; port AR_SDA
NetC84_2: C84.2 R183.1 U11.5(V+)
NetC85_1: C85.1 R187.1 U12.5(V+)
NetR179_1: R179.1 U11.3(ALERT)
NetR180_2: R180.2 U11.1(SCL)
NetR181_1: R181.1 U11.4(ADD0)
NetR182_1: R182.1 U11.6(SDA)
NetR184_1: R184.1 U12.3(ALERT)
NetR185_2: R185.2 U12.1(SCL)
NetR186_1: R186.1 U12.6(SDA)
NetR188_2: R188.2 U12.4(ADD0)

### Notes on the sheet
- ONBOARD TEMP SENSORS
- TEMP SENSOR CLOSE TO PMIC
- DEFAULT I2C ADDRESS 0X48
- TEMP SENSOR AWAY FROM PMIC
- DEFAULT I2C ADDRESS 0X49

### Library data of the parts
C84 C85 = CMP-0078241-1: as C67 on sheet PROC010C_XDS110 Interface_1B
R179 R184 = CMP-0025958-3: as R155 on sheet PROC010C_XDS110 Interface_1B
R180-R182 R185 R186 R188 = CMP-0027008-4: as R135 on sheet PROC010C_XDS110 Interface_1B
R183 R187 = CMP-0026992-2: as R128 on sheet PROC010C_XDS110 Interface_1B
U11 U12 = CMP-0067397-2: 1.4V-Capable +/-0.5degC Temperature Sensor with Alert Function and I2C/SMBus interface in SOT-563, DRL0006A (SOT-OTHER-6); Alternate PartNumber: TMP112AIDRLT; Alternate Manufacturer: Texas Instruments; Green_Lifecycle: Active; SizeAreaWB_mm2: 6.76; Green_REACh: Passed; U/M: EA; SizeZ_mm: 0.6; SizeX_mm: 1.6; SizeArea_mm2: 2.56; CompType: IC

## Sheet PROC010C_Hardware.SchDoc: Hardware
size 431 x 279 mm; Date: Not shown in title block; ApprovedBy: Not shown in title block; CheckedBy: Not shown in title block; Author: Not shown in title block; CompanyName: Not shown in title block; DrawnBy: Adrian Ozer; Engineer: Not shown in title block; Organization: Not shown in title block; Address1: Not shown in title block; Address2: Not shown in title block; Address3: Not shown in title block; Address4: Not shown in title block; DocumentNumber: 16; Revision: Use project parameter SCH_Rev; SheetNumber: 16; SheetTotal: 16; PageSetup: Record=PageOptions¦CenterHorizontal=True¦CenterVertical=True¦PrintScale=1.00¦XCorrection=1.00¦YCorrection=1.00¦PrintKind=0¦BorderSize=5000000¦LeftOffset=0¦BottomOffset=0¦Orientation=2¦PaperLength=1000¦PaperWidth=1000¦Scale=100¦PaperSource=15¦PrintQuality=600¦MediaType=1¦DitherType=10¦PaperKind=Letter¦PrintScaleMode=1
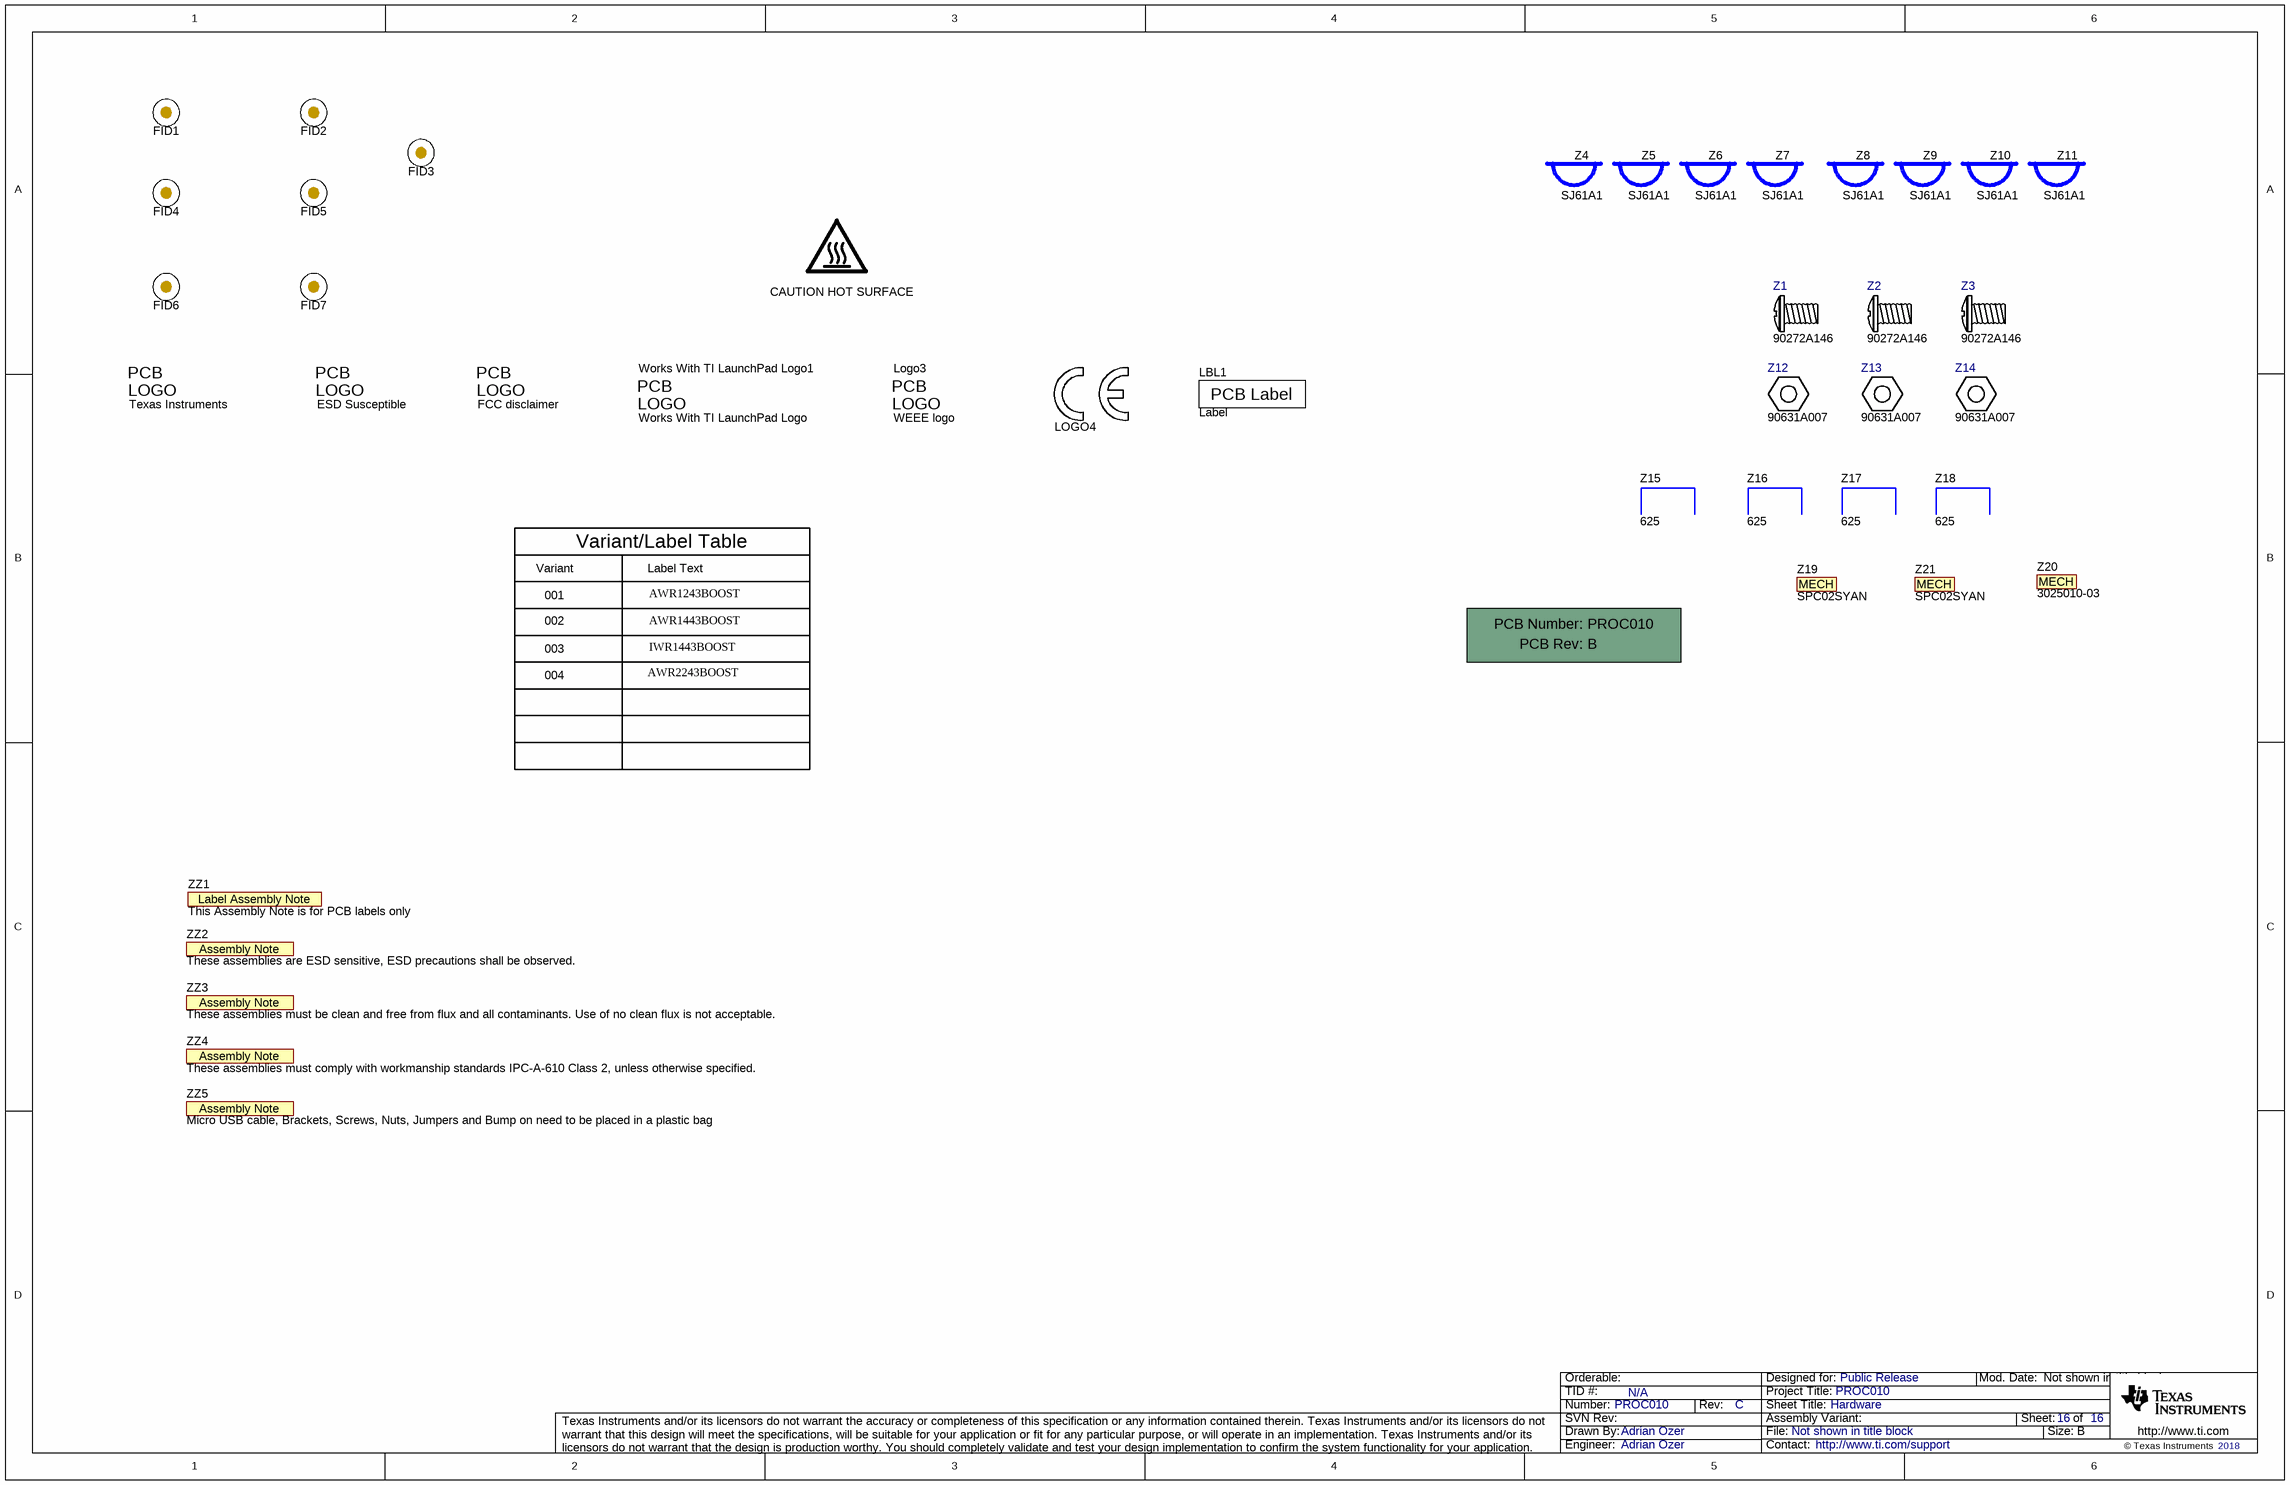
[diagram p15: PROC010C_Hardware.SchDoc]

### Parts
!PCB1  PROC010  (value not drawn)  (mechanical)
CAUTION_HOT_SURFACE1  CAUTION HOT SURFACE  [IEC_HotSurface_Small]  (no BOM)
ESD_Susceptible1  ESD Susceptible  [ESD_Overlay_Small]  (no BOM)
FID1  Fiducial  [Fiducial10-20]  (value not drawn)
FID2  Fiducial  [Fiducial10-20]  (value not drawn)
FID3  Fiducial  [Fiducial10-20]  (value not drawn)
FID4  Fiducial  [Fiducial10-20]  (value not drawn)
FID5  Fiducial  [Fiducial10-20]  (value not drawn)
FID6  Fiducial  [Fiducial10-20]  (value not drawn)
FID7  Fiducial  [Fiducial10-20]  (value not drawn)
LBL1  Label  [Label_650x200]
Logo1  Texas Instruments  [TI_Stacked_Overlay_Small]  (no BOM)
Logo2  FCC disclaimer  [FCC_disclaimer]  (no BOM)
Logo3  WEEE logo  [WEEE_Minimum]  (no BOM)
LOGO4  CE Mark  [CE_Mark_5mm]  (value not drawn)  (no BOM)
Works_With_TI_LaunchPad_Logo1  Works With TI LaunchPad Logo  [WorksWithTILaunchPad]  (no BOM)
Z1  90272A146  (mechanical)
Z2  90272A146  (mechanical)
Z3  90272A146  (mechanical)
Z4  SJ61A1  (mechanical)
Z5  SJ61A1  (mechanical)
Z6  SJ61A1  (mechanical)
Z7  SJ61A1  (mechanical)
Z8  SJ61A1  (mechanical)
Z9  SJ61A1  (mechanical)
Z10  SJ61A1  (mechanical)
Z11  SJ61A1  (mechanical)
Z12  90631A007  (mechanical)
Z13  90631A007  (mechanical)
Z14  90631A007  (mechanical)
Z15  625  (mechanical)
Z16  625  (mechanical)
Z17  625  (mechanical)
Z18  625  (mechanical)
Z19  SPC02SYAN  (mechanical)
Z20  3025010-03  (mechanical)
Z21  SPC02SYAN  (mechanical)
ZZ1  This Assembly Note is for PCB labels only  [AssemblyNoteLabel]  (no BOM)
ZZ2  These assemblies are ESD sensitive, ESD precautions shall be observed.  [AssemblyNote]  (no BOM)
ZZ3  These assemblies must be clean and free from flux and all contaminants. Use of no clean flux is not acceptable.  [AssemblyNote]  (no BOM)
ZZ4  These assemblies must comply with workmanship standards IPC-A-610 Class 2, unless otherwise specified.  [AssemblyNote]  (no BOM)
ZZ5  Micro USB cable, Brackets, Screws, Nuts, Jumpers and Bump on need to be placed in a plastic bag  [AssemblyNote]  (no BOM)

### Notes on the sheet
- Variant
- Variant/Label Table
- Label Text
- 001
- 002
- AWR1243BOOST
- AWR1443BOOST
- 003
- 004
- AWR2243BOOST
- IWR1443BOOST

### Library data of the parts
!PCB1 = CMP-0003618-2: Printed Circuit Board; Manufacturer: Any; CompType: PCB
CAUTION_HOT_SURFACE1 = CMP-0074837-1: IEC 61010-1 Hot Surface Warning; Library Reference: IEC_HotSurface; SymbolCreator: a0412235
ESD_Susceptible1 = CMP-0074840-1: ESD Susceptible Symbol; Library Reference: Logo; SymbolCreator: a0412235; Lib Reference: ESD_Susceptible
FID1-FID7 = CMP-0077181-1: Fiducial mark.  There is nothing to buy or mount.
LBL1 = CMP-0003625-1: Thermal Transfer Printable Labels, 0.650" W x 0.200" H - 10,000 per roll; Manufacturer: Brady; PartNumber: THT-14-423-10; Note: Size: 0.65" x 0.20 "
Logo1 = CMP-0074838-1: Texas Instrument Corporate Signature; SymbolCreator: a0412235; Lib Reference: TI_Logo; Library Reference: Logo
Logo2 = CMP-0074847-1: FCC_disclaimer; Library Reference: Logo
Logo3 = CMP-0074769-1
LOGO4 = CMP-0074844-1: SymbolCreator: a0412235
Works_With_TI_LaunchPad_Logo1 = CMP-0077108-1
Z1-Z3 = NY PMS 256 0050 PH: Screw, Pan Philips, Steel, 6-32; Manufacturer: McMaster-Carr; SymbolCreator: a0412235
Z4-Z11 = SJ61A1: Bumpon, Cylindrical, 0.312 X 0.200, Black; Manufacturer: 3M; SymbolCreator: a0412235; Green_Lifecycle: Not Set; Green_REACh: Incomplete
Z12-Z14 = HNSS 832: Nut, Hex, Steel Nylon-Insert, 6-32; Manufacturer: mcmaster
Z15-Z18 = PCC-SMP-CLIP: BRACKET MOUNTIG ALUM; Manufacturer: Keystone Electronics; CompType: Hardware
Z19 Z21 = 0050579402: 2 (1 x 2) Position Shunt Connector Black Closed Top 0.100" (2.54mm) Gold
Z20 = AK672M/2-1-R: CABLE MINI USB 5PIN 1M 2.0 VERS; CompType: CABLE USB
ZZ1 = CMP-0003616-3
ZZ2 = CMP-0077236-1
ZZ3 = CMP-0077237-1
ZZ4 = CMP-0077238-1
ZZ5 = CMP-0077238-1: Micro USB cable, Brackets, Screws, Nuts, Jumpers and Bump on need to be placed in a platic bag

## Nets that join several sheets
3V3_BRD: PROC010C_XDS110 Interface_1A (11 pins), PROC010C_XDS110 Interface_1B (20 pins), PROC010C_Tempsensor (5 pins)
5V_IN: PROC010C_PMIC_Reference (R149.2), PROC010C_Pwr_RST_LEDs (7 pins), PROC010C_HD Connector (R34.2), PROC010C_LP Connector (R115.2), PROC010C_XDS110 Interface_1A (R176.2), PROC010C_CAN Interface (R78.2)
5V_UNREG: PROC010C_PMIC_Reference (10 pins), PROC010C_Pwr_RST_LEDs (P5.2 R118.2)
+3.3VD: PROC010C_DUT_Reference (7 pins), PROC010C_Decoupling_Caps_Reference (C5.1), PROC010C_SOP_Headers_Reference (P2.2 P3.2 P4.2), PROC010C_QSPI_Flash_Reference (R37.1 R38.2 R41.2 R43.2), PROC010C_Pwr_RST_LEDs (6 pins), PROC010C_LP Connector (R172.2 R173.2), PROC010C_CAN Interface (6 pins)
AR_1P3_RF1: PROC010C_DUT_Reference (U2.G5 U2.H5 U2.J5), PROC010C_Decoupling_Caps_Reference (C45.1 C47.1), PROC010C_LC_Filtering_Reference (C36.2 C38.2 L5.2), PROC010C_LDO (5 pins)
AR_1P3_RF2: PROC010C_DUT_Reference (U2.C2 U2.D2), PROC010C_Decoupling_Caps_Reference (C57.1 C58.1), PROC010C_LC_Filtering_Reference (C33.2 C34.2 L8.2 R137.1), PROC010C_LDO (5 pins)
AR_1V2: PROC010C_DUT_Reference (6 pins), PROC010C_Decoupling_Caps_Reference (C3.1 C4.1 C6.1 C7.1), PROC010C_LC_Filtering_Reference (L9.2)
AR_1V4_APLL: PROC010C_DUT_Reference (U2.A10), PROC010C_Decoupling_Caps_Reference (C13.1)
AR_1V4_SYNTH: PROC010C_DUT_Reference (U2.A13), PROC010C_Decoupling_Caps_Reference (C14.1)
AR_1V8: PROC010C_DUT_Reference (6 pins), PROC010C_Decoupling_Caps_Reference (7 pins), PROC010C_LC_Filtering_Reference (C19.1 C91.2 L7.2), PROC010C_LDO (C18.1 R82.2 U4.1 U4.2)
AR_VBGAP: PROC010C_DUT_Reference (U2.B10), PROC010C_Decoupling_Caps_Reference (C56.1)
AR_VOUT_PA: PROC010C_DUT_Reference (U2.A2 U2.B2), PROC010C_Decoupling_Caps_Reference (C10.1 C65.1 C83.1), PROC010C_LC_Filtering_Reference (R137.2)
GND: PROC010C_DUT_Reference (81 pins), PROC010C_Decoupling_Caps_Reference (22 pins), PROC010C_PMIC_Reference (20 pins), PROC010C_LC_Filtering_Reference (6 pins), PROC010C_SOP_Headers_Reference (R88.1 R96.1 R114.1), PROC010C_QSPI_Flash_Reference (C1.1 C2.1 U1.4 U1.9), PROC010C_Pwr_RST_LEDs (14 pins), PROC010C_LDO (23 pins), PROC010C_HD Connector (14 pins), PROC010C_LP Connector (7 pins), PROC010C_XDS110 Interface_1A (22 pins), PROC010C_XDS110 Interface_1B (21 pins), PROC010C_CAN Interface (10 pins), PROC010C_Tempsensor (5 pins)
MCU_3V3: PROC010C_Pwr_RST_LEDs (R130.1), PROC010C_LP Connector (J4.3 J5.1)
PMIC_1V0: PROC010C_PMIC_Reference (C81.2 L4.2 U8.1), PROC010C_LC_Filtering_Reference (L5.1 L8.1), PROC010C_LDO (10 pins)
PMIC_1V2: PROC010C_PMIC_Reference (C54.2 L1.2 U8.14), PROC010C_LC_Filtering_Reference (L9.1)
PMIC_1V8: PROC010C_PMIC_Reference (C82.2 L3.2 U8.21), PROC010C_LC_Filtering_Reference (L7.1), PROC010C_LDO (6 pins)
PMICOUT_3V3: PROC010C_PMIC_Reference (C55.2 L2.2 R141.1 U8.8), PROC010C_Pwr_RST_LEDs (R133.1)
VDDC_1: PROC010C_XDS110 Interface_1A (C62.2 C64.2 C74.2 C75.2), PROC010C_XDS110 Interface_1B (U6.87 U6.115)
XDSET_1_VBUS: PROC010C_XDS110 Interface_1A (R151.2 R161.2 U10.6), PROC010C_XDS110 Interface_1B (R154.2)
AR_ANAMUX: PROC010C_DUT_Reference (U2.C13), PROC010C_LP Connector (P1.3)
AR_ANATEST1: PROC010C_DUT_Reference (U2.P1), PROC010C_LP Connector (R104.2)
AR_ANATEST2: PROC010C_DUT_Reference (U2.P2), PROC010C_LP Connector (R94.2)
AR_ANATEST3: PROC010C_DUT_Reference (U2.P3), PROC010C_LP Connector (R105.2)
AR_ANATEST4: PROC010C_DUT_Reference (U2.R2), PROC010C_LP Connector (R106.2)
AR_BSS_LOGGER: PROC010C_DUT_Reference (U2.R4), PROC010C_LP Connector (R31.1), PROC010C_XDS110 Interface_1B (R135.1)
AR_CS1: PROC010C_DUT_Reference (U2.R7), PROC010C_CAN Interface (U13.10)
AR_GPIO_0: PROC010C_DUT_Reference (U2.N4), PROC010C_LP Connector (R164.1), PROC010C_CAN Interface (R177.2)
AR_GPIO_1: PROC010C_DUT_Reference (U2.N7), PROC010C_Pwr_RST_LEDs (R72.2), PROC010C_LP Connector (R9.2)
AR_GPIO_2: PROC010C_DUT_Reference (U2.N13), PROC010C_Pwr_RST_LEDs (R110.2 R116.1), PROC010C_LP Connector (R8.2)
AR_HOSTINTR1: PROC010C_DUT_Reference (R13.2 U2.P6), PROC010C_HD Connector (R64.2), PROC010C_LP Connector (R10.2)
AR_LVDS_VALID_N: PROC010C_DUT_Reference (U2.N14), PROC010C_HD Connector (R60.2)
AR_LVDS_VALID_P: PROC010C_DUT_Reference (U2.N15), PROC010C_HD Connector (R61.2)
AR_LVDSCSI0_N: PROC010C_DUT_Reference (U2.G14), PROC010C_HD Connector (R48.2)
AR_LVDSCSI0_P: PROC010C_DUT_Reference (U2.G15), PROC010C_HD Connector (R49.2)
AR_LVDSCSI1_N: PROC010C_DUT_Reference (U2.H14), PROC010C_HD Connector (R50.2)
AR_LVDSCSI1_P: PROC010C_DUT_Reference (U2.H15), PROC010C_HD Connector (R51.2)
AR_LVDSCSI2_N: PROC010C_DUT_Reference (U2.K14), PROC010C_HD Connector (R54.2)
AR_LVDSCSI2_P: PROC010C_DUT_Reference (U2.K15), PROC010C_HD Connector (R55.2)
AR_LVDSCSI3_N: PROC010C_DUT_Reference (U2.L14), PROC010C_HD Connector (R56.2)
AR_LVDSCSI3_P: PROC010C_DUT_Reference (U2.L15), PROC010C_HD Connector (R57.2)
AR_LVDSCSI_CLK_N: PROC010C_DUT_Reference (U2.J14), PROC010C_HD Connector (R52.2)
AR_LVDSCSI_CLK_P: PROC010C_DUT_Reference (U2.J15), PROC010C_HD Connector (R53.2)
AR_LVDSCSI_FRCLK_N: PROC010C_DUT_Reference (U2.M14), PROC010C_HD Connector (R58.2)
AR_LVDSCSI_FRCLK_P: PROC010C_DUT_Reference (U2.M15), PROC010C_HD Connector (R59.2)
AR_MCUCLKOUT: PROC010C_DUT_Reference (U2.N9), PROC010C_LP Connector (R25.1)
AR_MISO1: PROC010C_DUT_Reference (U2.P5), PROC010C_CAN Interface (U13.2)
AR_MOSI1: PROC010C_DUT_Reference (U2.R8), PROC010C_CAN Interface (U13.5)
AR_MSS_LOGGER: PROC010C_DUT_Reference (U2.R5), PROC010C_LP Connector (R26.1), PROC010C_XDS110 Interface_1B (R136.1)
AR_NERR_OUT: PROC010C_DUT_Reference (R91.1 U2.N8), PROC010C_Pwr_RST_LEDs (DS1.2), PROC010C_HD Connector (R7.2), PROC010C_LP Connector (R19.1)
AR_NERRIN: PROC010C_DUT_Reference (R16.1 U2.P7), PROC010C_LP Connector (R24.1)
AR_NRST: PROC010C_DUT_Reference (U2.P12), PROC010C_Pwr_RST_LEDs (6 pins)
AR_NRST_MCU: PROC010C_Pwr_RST_LEDs (R77.1), PROC010C_HD Connector (R20.1), PROC010C_LP Connector (R2.2)
AR_NRST_XDS: PROC010C_Pwr_RST_LEDs (R80.1), PROC010C_XDS110 Interface_1B (U6.40)
AR_OSC_CLKOUT: PROC010C_DUT_Reference (U2.A14), PROC010C_HD Connector (R111.1)
AR_PMIC_CLKOUT_SOP2: PROC010C_DUT_Reference (U2.P13), PROC010C_SOP_Headers_Reference (R97.1 R98.1), PROC010C_LP Connector (R109.2)
AR_QSPI_CS: PROC010C_DUT_Reference (U2.P8), PROC010C_QSPI_Flash_Reference (R38.1 U1.1)
AR_QSPI_D0: PROC010C_DUT_Reference (U2.R11), PROC010C_QSPI_Flash_Reference (R45.2)
AR_QSPI_D1: PROC010C_DUT_Reference (U2.P9), PROC010C_QSPI_Flash_Reference (R39.1)
AR_QSPI_D2: PROC010C_DUT_Reference (U2.R12), PROC010C_QSPI_Flash_Reference (R42.1 R43.1)
AR_QSPI_D3: PROC010C_DUT_Reference (U2.P10), PROC010C_QSPI_Flash_Reference (R40.2 R41.1)
AR_QSPI_SCLK: PROC010C_DUT_Reference (U2.R10), PROC010C_QSPI_Flash_Reference (R44.2)
AR_RS232RX: PROC010C_DUT_Reference (U2.N5), PROC010C_HD Connector (R33.1), PROC010C_LP Connector (R166.1 R168.1 R172.1), PROC010C_XDS110 Interface_1B (R129.1)
AR_RS232TX: PROC010C_DUT_Reference (U2.N6), PROC010C_HD Connector (R21.1), PROC010C_LP Connector (R167.1 R169.1 R173.1), PROC010C_XDS110 Interface_1B (R128.1)
AR_SCL: PROC010C_DUT_Reference (R171.1 R197.1), PROC010C_PMIC_Reference (R144.1), PROC010C_HD Connector (R22.1), PROC010C_LP Connector (R163.1), PROC010C_Tempsensor (R180.1 R185.1)
AR_SDA: PROC010C_DUT_Reference (R170.1 R198.1), PROC010C_PMIC_Reference (R146.2), PROC010C_HD Connector (R23.1), PROC010C_LP Connector (R162.1), PROC010C_Tempsensor (R182.2 R186.2)
AR_SPICLK1: PROC010C_DUT_Reference (U2.R9), PROC010C_CAN Interface (U13.7)
AR_SYNC_IN: PROC010C_DUT_Reference (R196.2 U2.N10), PROC010C_HD Connector (R62.2), PROC010C_LP Connector (R165.1)
AR_SYNC_OUT_SOP1: PROC010C_DUT_Reference (U2.P11), PROC010C_SOP_Headers_Reference (R113.1), PROC010C_LP Connector (R108.2)
AR_TCK: PROC010C_DUT_Reference (U2.M13), PROC010C_HD Connector (R66.2 R70.1)
AR_TDI: PROC010C_DUT_Reference (U2.H13), PROC010C_HD Connector (R29.1 R30.1)
AR_TDO_SOP0: PROC010C_DUT_Reference (U2.J13), PROC010C_SOP_Headers_Reference (R89.1), PROC010C_HD Connector (R67.2 R71.1)
AR_TMS: PROC010C_DUT_Reference (U2.L13), PROC010C_HD Connector (R65.2 R69.1)
AR_VSENSE: PROC010C_DUT_Reference (U2.C14), PROC010C_LP Connector (P1.1)
AR_WARMRST: PROC010C_DUT_Reference (R15.1 U2.N12), PROC010C_Pwr_RST_LEDs (DS5.2), PROC010C_LP Connector (R18.1)
CS1: PROC010C_DUT_Reference (R14.1), PROC010C_HD Connector (R17.1), PROC010C_LP Connector (R1.2), PROC010C_CAN Interface (U13.11)
MCU_SOP0: PROC010C_SOP_Headers_Reference (R93.2), PROC010C_LP Connector (R36.1)
MCU_SOP1: PROC010C_SOP_Headers_Reference (R112.2), PROC010C_LP Connector (R35.1)
MCU_SOP2: PROC010C_SOP_Headers_Reference (R101.2), PROC010C_LP Connector (R32.1)
MISO1: PROC010C_HD Connector (R63.2), PROC010C_LP Connector (R3.2 R6.2), PROC010C_CAN Interface (U13.1)
MOSI1: PROC010C_HD Connector (R28.1), PROC010C_LP Connector (R4.2 R5.2), PROC010C_CAN Interface (U13.4)
PGOOD: PROC010C_PMIC_Reference (R138.2 R141.2), PROC010C_HD Connector (R27.1), PROC010C_LP Connector (R107.2), PROC010C_XDS110 Interface_1A (R159.1)
PMIC_CLK: PROC010C_PMIC_Reference (U8.3), PROC010C_SOP_Headers_Reference (R97.2)
PMIC_EN1: PROC010C_PMIC_Reference (R142.1 U8.7), PROC010C_LP Connector (R102.2)
SPICLK1: PROC010C_HD Connector (R75.1), PROC010C_LP Connector (R76.1), PROC010C_CAN Interface (U13.8)
VBUS_1_DETECT: PROC010C_XDS110 Interface_1A (C69.2 R151.1 R153.2), PROC010C_XDS110 Interface_1B (U6.1)
XDSET_1_D_N: PROC010C_XDS110 Interface_1A (J8.2 U10.1), PROC010C_XDS110 Interface_1B (U6.93)
XDSET_1_D_P: PROC010C_XDS110 Interface_1A (J8.3 U10.4), PROC010C_XDS110 Interface_1B (U6.94)
XDSET_1_ID: PROC010C_XDS110 Interface_1A (J8.4 U10.2), PROC010C_XDS110 Interface_1B (R152.2)
XDSET_TCK: PROC010C_HD Connector (R70.2), PROC010C_XDS110 Interface_1B (U6.35)
XDSET_TDI: PROC010C_HD Connector (R30.2), PROC010C_XDS110 Interface_1B (U6.38)
XDSET_TDO: PROC010C_HD Connector (R71.2), PROC010C_XDS110 Interface_1B (U6.37)
XDSET_TMS: PROC010C_HD Connector (R69.2), PROC010C_XDS110 Interface_1B (U6.36)

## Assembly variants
001: not fitted C8 C18 C21 C22 C23 C25 C28 C29 C30 C31 C32 C35 C37 C40 C44 C46 C83 FB2 FID1 FID2 FID3 FID4 FID5 FID6 FID7 R3 R5 R8 R9 R21 R26 R33 R46 R47 R81 R82 R83 R84 R97 R102 R108 R109 R115 R119 R120 R121 R122 R130 R131 R132 R135 R164 R166 R167 R168 R169 R177 R178 R197 R198 TP1 TP2 U4 U5
002: not fitted C8 C18 C21 C22 C23 C25 C28 C29 C30 C31 C32 C35 C37 C40 C44 C46 C83 FB2 FID1 FID2 FID3 FID4 FID5 FID6 FID7 R3 R5 R8 R9 R21 R26 R33 R46 R47 R81 R82 R83 R84 R97 R102 R108 R109 R115 R119 R120 R121 R122 R130 R131 R132 R135 R164 R166 R167 R168 R169 R177 R178 R197 R198 TP1 TP2 U4 U5
003: not fitted C8 C18 C21 C22 C23 C25 C28 C29 C30 C31 C32 C35 C37 C40 C44 C46 C83 FB2 FID1 FID2 FID3 FID4 FID5 FID6 FID7 R3 R5 R8 R9 R21 R26 R33 R46 R47 R81 R82 R83 R84 R97 R102 R108 R109 R115 R119 R120 R121 R122 R130 R131 R132 R135 R164 R166 R167 R168 R169 R177 R178 R197 R198 TP1 TP2 U4 U5
004: not fitted C8 C18 C21 C22 C23 C25 C28 C29 C30 C31 C32 C35 C37 C40 C44 C46 C83 FB2 FID1 FID2 FID3 FID4 FID5 FID6 FID7 R3 R5 R8 R9 R21 R26 R33 R46 R47 R81 R82 R83 R84 R97 R102 R108 R109 R115 R119 R120 R121 R122 R130 R131 R132 R135 R164 R166 R167 R168 R169 R177 R178 R197 R198 TP1 TP2 U4 U5; alternate parts U2 -> CMP-0082537-1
